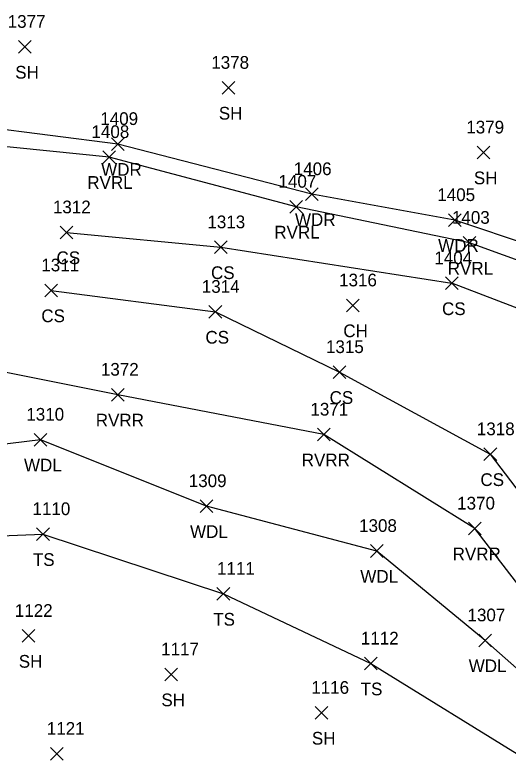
# Model space of a CAD drawing. Extents: x 1621633 to 1624015, y 417863 to 420979.
# Drawn here: x 1622113.6 to 1622191.2, y 418184 to 418301.5 of the extents above; entities that cross this region are included whole.
import ezdxf

# ---------------------------------------------------------------- set-up
doc = ezdxf.new("R2010")
doc.units = 0
for name, color, linetype in [('L_A', 7, 'Continuous'), ('L_I', 7, 'Continuous'), ('L_TIC', 7, 'Continuous'), ('LAWA', 7, 'Continuous'), ('LAWE', 7, 'Continuous'), ('LELB', 7, 'Continuous')]:
    doc.layers.add(name, color=color, linetype=linetype)

msp = doc.modelspace()

# ---------------------------------------------------------------- linework, layer by layer
at = {"layer": 'L_TIC'}
for points in [[(1622114.17, 418295.46), (1622116.17, 418297.46)], [(1622116.17, 418295.46), (1622114.17, 418297.46)], [(1622146.2, 418289.01), (1622148.2, 418291.01)], [(1622148.2, 418289.01), (1622146.2, 418291.01)], [(1622128.81, 418280.16), (1622130.81, 418282.16)], [(1622130.81, 418280.16), (1622128.81, 418282.16)], [(1622186.33, 418278.83), (1622188.33, 418280.83)], [(1622188.33, 418278.83), (1622186.33, 418280.83)], [(1622127.42, 418278.11), (1622129.42, 418280.11)], [(1622129.42, 418278.11), (1622127.42, 418280.11)], [(1622159.31, 418272.27), (1622161.31, 418274.27)], [(1622161.31, 418272.27), (1622159.31, 418274.27)], [(1622156.85, 418270.29), (1622158.85, 418272.29)], [(1622158.85, 418270.29), (1622156.85, 418272.29)], [(1622181.84, 418268.19), (1622183.84, 418270.19)], [(1622183.84, 418268.19), (1622181.84, 418270.19)], [(1622120.7, 418266.26), (1622122.7, 418268.26)], [(1622122.7, 418266.26), (1622120.7, 418268.26)], [(1622184.14, 418264.61), (1622186.14, 418266.61)], [(1622186.14, 418264.61), (1622184.14, 418266.61)], [(1622145.02, 418263.91), (1622147.02, 418265.91)], [(1622147.02, 418263.91), (1622145.02, 418265.91)], [(1622181.37, 418258.24), (1622183.37, 418260.24)], [(1622183.37, 418258.24), (1622181.37, 418260.24)], [(1622118.32, 418257.12), (1622120.32, 418259.12)], [(1622120.32, 418257.12), (1622118.32, 418259.12)], [(1622165.79, 418254.76), (1622167.79, 418256.76)], [(1622167.79, 418254.76), (1622165.79, 418256.76)], [(1622144.14, 418253.74), (1622146.14, 418255.74)], [(1622146.14, 418253.74), (1622144.14, 418255.74)], [(1622163.68, 418244.26), (1622165.68, 418246.26)], [(1622165.68, 418244.26), (1622163.68, 418246.26)], [(1622128.82, 418240.7), (1622130.82, 418242.7)], [(1622130.82, 418240.7), (1622128.82, 418242.7)], [(1622116.62, 418233.62), (1622118.62, 418235.62)], [(1622118.62, 418233.62), (1622116.62, 418235.62)], [(1622161.23, 418234.42), (1622163.23, 418236.42)], [(1622163.23, 418234.42), (1622161.23, 418236.42)], [(1622187.41, 418231.33), (1622189.41, 418233.33)], [(1622189.41, 418231.33), (1622187.41, 418233.33)], [(1622142.74, 418223.16), (1622144.74, 418225.16)], [(1622144.74, 418223.16), (1622142.74, 418225.16)], [(1622184.97, 418219.63), (1622186.97, 418221.63)], [(1622186.97, 418219.63), (1622184.97, 418221.63)], [(1622117.02, 418218.75), (1622119.02, 418220.75)], [(1622119.02, 418218.75), (1622117.02, 418220.75)], [(1622169.53, 418216.1), (1622171.53, 418218.1)], [(1622171.53, 418216.1), (1622169.53, 418218.1)], [(1622145.4, 418209.35), (1622147.4, 418211.35)], [(1622147.4, 418209.35), (1622145.4, 418211.35)], [(1622114.72, 418202.73), (1622116.72, 418204.73)], [(1622116.72, 418202.73), (1622114.72, 418204.73)], [(1622186.59, 418202.03), (1622188.59, 418204.03)], [(1622188.59, 418202.03), (1622186.59, 418204.03)], [(1622168.6, 418198.38), (1622170.6, 418200.38)], [(1622170.6, 418198.38), (1622168.6, 418200.38)], [(1622137.17, 418196.66), (1622139.17, 418198.66)], [(1622139.17, 418196.66), (1622137.17, 418198.66)], [(1622160.84, 418190.62), (1622162.84, 418192.62)], [(1622162.84, 418190.62), (1622160.84, 418192.62)], [(1622119.18, 418184.17), (1622121.18, 418186.17)], [(1622121.18, 418184.17), (1622119.18, 418186.17)]]:
    msp.add_lwpolyline(points, dxfattribs=at)
at = {"layer": 'LAWA'}
for points in [[(1622334.14, 418235.62), (1622304.57, 418226.13), (1622279.17, 418224.78), (1622252.77, 418236.61), (1622231.24, 418254.76), (1622207.28, 418260.97), (1622182.84, 418269.19), (1622160.31, 418273.27), (1622129.81, 418281.16), (1622108.44, 418283.87), (1622096.55, 418277.43), (1622071.98, 418274.52), (1622045.71, 418270.54), (1622021.3, 418265.82)], [(1622294.12, 418161.35), (1622295.35, 418165.31), (1622279.05, 418165.1), (1622262.62, 418162.03), (1622241.27, 418162.89), (1622220.84, 418170.43), (1622210.97, 418182.32), (1622187.59, 418203.03), (1622170.53, 418217.1), (1622143.74, 418224.16), (1622117.62, 418234.62), (1622098.7, 418232.3), (1622072.64, 418230.63)]]:
    msp.add_lwpolyline(points, dxfattribs=at)
at = {"layer": 'LAWE'}
for points in [[(1622333.17, 418232.98), (1622304.92, 418224.43), (1622278.58, 418222.6), (1622250.59, 418234.06), (1622231.09, 418250.9), (1622207.09, 418257.63), (1622185.14, 418265.61), (1622157.85, 418271.29), (1622128.42, 418279.11), (1622109.18, 418281.03), (1622103.42, 418276.53), (1622081.07, 418269.59), (1622054.89, 418266.85), (1622024.68, 418262.78), (1621999.35, 418261.34), (1621980.1, 418259.35), (1621959.54, 418247.53), (1621949.11, 418230.91), (1621945.67, 418206.62), (1621950.84, 418182.3), (1621958.69, 418157.04), (1621962.92, 418133.77), (1621970.23, 418110.89)], [(1622323.31, 418180.93), (1622300.82, 418170.32), (1622276.31, 418168.44), (1622241.72, 418167.29), (1622221.82, 418173.51), (1622205.88, 418194.82), (1622185.97, 418220.63), (1622162.23, 418235.42), (1622129.82, 418241.7), (1622106.38, 418246.35), (1622101.43, 418250.25), (1622073.09, 418248.58), (1622043.82, 418244.16), (1622014.93, 418241.31), (1621989.87, 418234.25), (1621972.68, 418220.99), (1621964.49, 418204.33), (1621969.88, 418176.14), (1621978.91, 418154.62), (1621984.37, 418139.62), (1621989.94, 418122.86), (1621991.15, 418115.14)]]:
    msp.add_lwpolyline(points, dxfattribs=at)
at = {"layer": 'LELB'}
for points in [[(1622121.7, 418267.26), (1622146.02, 418264.91)], [(1622146.02, 418264.91), (1622182.37, 418259.24)], [(1622226.07, 418242.54), (1622182.37, 418259.24)], [(1622119.32, 418258.12), (1622145.14, 418254.74), (1622164.68, 418245.26), (1622188.41, 418232.33), (1622207.08, 418207.82), (1622220.43, 418193.23), (1622238.89, 418176.95)], [(1622012.96, 418144.68), (1622025.55, 418152.7), (1622030.18, 418148.41), (1622040.54, 418132.85), (1622043.38, 418133.51), (1622037.79, 418144.79), (1622034.62, 418151.12), (1622038.47, 418156.73), (1622040.15, 418173.27), (1622045.7, 418182.18), (1622058.58, 418190.33), (1622063.65, 418207.42), (1622064.55, 418215.49), (1622074.9, 418223.54), (1622095.34, 418218.88), (1622118.02, 418219.75), (1622146.4, 418210.35), (1622169.6, 418199.38), (1622194.43, 418184.07), (1622206.1, 418163.37)]]:
    msp.add_lwpolyline(points, dxfattribs=at)

# ---------------------------------------------------------------- texts
at = {"layer": 'L_A'}
for s, p in [('SH', (1622113.65, 418291.46)), ('SH', (1622145.69, 418285.01)), ('WDR', (1622127.18, 418276.16)), ('SH', (1622185.82, 418274.83)), ('RVRL', (1622124.99, 418274.11)), ('WDR', (1622157.67, 418268.27)), ('RVRL', (1622154.42, 418266.29)), ('WDR', (1622180.2, 418264.19)), ('CS', (1622120.15, 418262.26)), ('RVRL', (1622181.71, 418260.61)), ('CS', (1622144.46, 418259.91)), ('CS', (1622180.81, 418254.24)), ('CS', (1622117.76, 418253.12)), ('CH', (1622165.28, 418250.76)), ('CS', (1622143.58, 418249.74)), ('CS', (1622163.12, 418240.26)), ('RVRR', (1622126.33, 418236.7)), ('RVRR', (1622158.74, 418230.42)), ('WDL', (1622115.03, 418229.62)), ('CS', (1622186.85, 418227.33)), ('WDL', (1622141.16, 418219.16)), ('TS', (1622116.43, 418214.75)), ('RVRR', (1622182.48, 418215.63)), ('WDL', (1622167.95, 418212.1)), ('TS', (1622144.81, 418205.35)), ('SH', (1622114.21, 418198.73)), ('WDL', (1622185.01, 418198.03)), ('TS', (1622168.01, 418194.38)), ('SH', (1622136.65, 418192.66)), ('SH', (1622160.33, 418186.62))]:
    msp.add_text(s, height=2, dxfattribs=at).set_placement(p)
at = {"layer": 'L_I'}
for s, p in [('1377', (1622112.47, 418299.46)), ('1378', (1622144.5, 418293.01)), ('1409', (1622127.04, 418284.16)), ('1408', (1622125.65, 418282.11)), ('1379', (1622184.63, 418282.83)), ('1406', (1622157.48, 418276.27)), ('1407', (1622155.08, 418274.29)), ('1405', (1622180.07, 418272.19)), ('1312', (1622119.58, 418270.26)), ('1313', (1622143.89, 418267.91)), ('1403', (1622182.37, 418268.61)), ('1404', (1622179.6, 418262.24)), ('1311', (1622117.76, 418261.12)), ('1316', (1622164.61, 418258.76)), ('1314', (1622143.01, 418257.74)), ('1315', (1622162.55, 418248.26)), ('1372', (1622127.13, 418244.7)), ('1371', (1622160.1, 418238.42)), ('1310', (1622115.4, 418237.62)), ('1318', (1622186.29, 418235.33)), ('1309', (1622140.96, 418227.16)), ('1370', (1622183.19, 418223.63)), ('1110', (1622116.37, 418222.75)), ('1308', (1622167.76, 418220.1)), ('1111', (1622145.4, 418213.35)), ('1122', (1622113.59, 418206.73)), ('1307', (1622184.82, 418206.03)), ('1112', (1622168.04, 418202.38)), ('1117', (1622136.61, 418200.66)), ('1116', (1622160.23, 418194.62)), ('1121', (1622118.62, 418188.17))]:
    msp.add_text(s, height=2, dxfattribs=at).set_placement(p)

doc.saveas('drawing.dxf')
